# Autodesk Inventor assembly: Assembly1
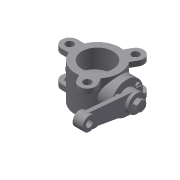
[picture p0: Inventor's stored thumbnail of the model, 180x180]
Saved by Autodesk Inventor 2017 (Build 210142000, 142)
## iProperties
Created: 2016-07
Part Number: Assembly1
Document SubType Name: Assembly
Designer: Sandeep
Author: Sandeep
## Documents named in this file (9)
- D:\KAVITA\Autodesk Inventor_2017_Project\Part's File\Inventor_2016_tut\c09_Inv_tut_2016\c09_tut01_inv\Butterfly Valve\OldVersions\Assembly1.iam
- D:\KAVITA\Autodesk Inventor_2017_Project\Part's File\Inventor_2016_tut\c09_Inv_tut_2016\c09_tut01_inv\Butterfly Valve\Body.ipt
- D:\KAVITA\Autodesk Inventor_2017_Project\Part's File\Inventor_2016_tut\c09_Inv_tut_2016\c09_tut01_inv\Butterfly Valve\shaft1.ipt
- D:\KAVITA\Autodesk Inventor_2017_Project\Part's File\Inventor_2016_tut\c09_Inv_tut_2016\c09_tut01_inv\Butterfly Valve\Arm1.ipt
- D:\KAVITA\Autodesk Inventor_2017_Project\Part's File\Inventor_2016_tut\c09_Inv_tut_2016\c09_tut01_inv\Butterfly Valve\Retainer.ipt
- D:\KAVITA\Autodesk Inventor_2017_Project\Part's File\Inventor_2016_tut\c09_Inv_tut_2016\c09_tut01_inv\Butterfly Valve\scew1.ipt
- D:\KAVITA\Autodesk Inventor_2017_Project\Part's File\Inventor_2016_tut\c09_Inv_tut_2016\c09_tut01_inv\Butterfly Valve\Plate.ipt
- D:\KAVITA\Autodesk Inventor_2017_Project\Part's File\Inventor_2016_tut\c09_Inv_tut_2016\c09_tut01_inv\Butterfly Valve\Screw.ipt
- D:\KAVITA\Autodesk Inventor_2017_Project\Part's File\Inventor_2016_tut\c09_Inv_tut_2016\c09_tut01_inv\Butterfly Valve\Nut.ipt
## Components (11 placed, 8 different names)
1. Body:2 — Mate:1, Insert:2, Insert:3, Angle:3, Insert:12
2. shaft1:1 — Angle:2, Angle:3, Insert:5, Insert:6, Insert:12, Insert:13
3. Retainer:1 — Mate:1, Insert:2, Insert:3, Insert:4, Angle:1, Insert:9, Insert:10, Insert:11
4. Arm1:2 — Insert:4, Angle:1, Angle:2
5. scew1:1 — Insert:7
6. scew1:2 — Insert:8
7. Plate:1 — Insert:5, Insert:6, Insert:7, Insert:8
8. Screw:1 — Insert:9
9. Screw:2 — Insert:10
10. Screw:3 — Insert:11
11. Nut:1 — Insert:13
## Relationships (16: Insert 12, Angle 3, Mate 1)
- Mate:1: Body:2 ↔ Retainer:1
- Insert:2: Body:2 ↔ Retainer:1
- Insert:3: Body:2 ↔ Retainer:1
- Insert:4: Retainer:1 ↔ Arm1:2
- Angle:1: Retainer:1 ↔ Arm1:2
- Angle:2: shaft1:1 ↔ Arm1:2
- Angle:3: Body:2 ↔ shaft1:1
- Insert:5: shaft1:1 ↔ Plate:1
- Insert:6: shaft1:1 ↔ Plate:1
- Insert:7: scew1:1 ↔ Plate:1
- Insert:8: scew1:2 ↔ Plate:1
- Insert:9: Retainer:1 ↔ Screw:1
- Insert:10: Retainer:1 ↔ Screw:2
- Insert:11: Retainer:1 ↔ Screw:3
- Insert:12: Body:2 ↔ shaft1:1
- Insert:13: shaft1:1 ↔ Nut:1
